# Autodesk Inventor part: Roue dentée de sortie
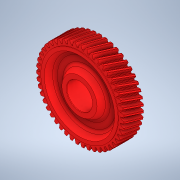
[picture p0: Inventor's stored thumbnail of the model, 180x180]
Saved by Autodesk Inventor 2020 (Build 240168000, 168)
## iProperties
Created: 2003-05
Part Number: Roue dentée de sortie
Material: Générique
Document SubType Name: Modeling
Designer: Bruno
Density: 1 g/cm^3
Appearance: Par défaut
Author: Bruno
Sending System: SolidWorks 2011
Last Author: frederic
Last Saved: 2012-02-20
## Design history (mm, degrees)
feature "Enlèvement de matière-Révolution1"
node "Solide1"
